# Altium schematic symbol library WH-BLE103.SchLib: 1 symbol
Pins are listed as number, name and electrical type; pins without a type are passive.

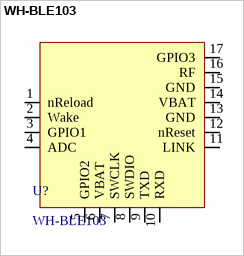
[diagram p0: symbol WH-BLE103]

## WH-BLE103
designator U?
footprint PCBComponent_1
pins: 1 nReload, 2 Wake, 3 GPIO1, 4 ADC, 5 GPIO2, 6 VBAT, 7 SWCLK, 8 SWDIO, 9 TXD, 10 RXD, 11 LINK, 12 nReset, 13 GND, 14 VBAT, 15 GND, 16 RF, 17 GPIO3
